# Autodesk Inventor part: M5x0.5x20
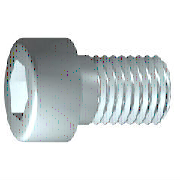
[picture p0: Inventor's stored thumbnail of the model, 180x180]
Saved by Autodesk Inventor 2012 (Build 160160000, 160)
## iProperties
IsCustomPart: 0
Company: 한국ATC센터
Created: 2014-07
Part Number: M5x0.5x20
Material: Steel, Mild
Description: 6각머리 태핑 나사
Document SubType Name: Modeling
Standard: KS B 1003
Designer: KYOUNG IL JANG
Standards Organization: KS
Language: ko-KR
Size Designation: M 5 x 20
Categories: <MemberInstance><Categories><Category DisplayName="조임쇠" InternalName="e4da775c-781d-43d5-af7c-5136215cf5a6" Mnemonic="FSTN"><Category DisplayName="볼트" InternalN
Density: 7.86 g/cm^3
Mass: 4.9629 g
Surface Area: 5.88237 cm^2
Volume: 0.631412 cm^3
Author: KYOUNG IL JANG
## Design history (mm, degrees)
body "Solid1"
workplane "Work Plane1"
fillet "Fillet2" dims "d30" = 0.1 (= R)
revolve "본체" stored, may be unused: angle "d10" = 90 deg
sketch "스케치2"
  geometry: L1 (0, -5.95)-(0, 5.95) reference; L2 (-5.95, 0)-(5.95, 0) reference; L3 (2.309, 0)-(1.155, -2); L4 (1.155, -2)-(-1.155, -2); L5 (-1.155, -2)-(-2.309, 0); L6 (-2.309, 0)-(-1.155, 2); L7 (-1.155, 2)-(1.155, 2); L8 (1.155, 2)-(2.309, 0); 2 further points
  constraints: 12 end point, 1 coincident, 1 horizontal alignment, 1 point on line, 12 other
extrude "슬롯" join sketch "스케치2" stored distance "d11" = 10; taper "d12" = 0 deg
fillet "모깎기1" dims "d17" = 0.5 (= RR)
feature "스레드" dims "d13" = 18 (= GEL), "d14" = 0
chamfer "모따기1" distance "d15" = 0.49076 (= -0.5 x SPD + 0.5 x GD); stored, may be unused: second distance "d16" = 0.49076 (= GUL), angle "d27" = 45 deg
sketch "스케치1"
  geometry: L1 (-1.167, 0)-(20, 0); L2 (20, 0)-(20, 2.5); L3 (20, 2.5)-(2, 2.5); L4 (2, 2.5)-(1.509, 2.5); L5 (1.509, 2.5)-(0, 2.5); L6 (0, 2.5)-(0, 4.25); L7 (0, 4.25)-(-5, 4.25); L8 (-5, 4.25)-(-5, 2.309); L9 (-5, 2.309)-(-2.5, 2.309); L10 (-2.5, 2.309)-(-1.167, 0); L11 (-10, 0)-(25, 0) reference; L12 (0, -0.85)-(0, 5.1) reference; L13 (2, 2.5)-(0, 2.5)
  constraints: 22 end point, 6 parallel, 2 collinear, 2 perpendicular, 1 horizontal, 1 point on line
  dimensions: "d1" = 18 distance from line of L3.end L2 (= GEL); "d2" = 0.49086 distance of L4.end L3.end (computed from GAL); "d3" = 5 distance between parallel lines of L8 L6 (= KOH); "d4" = 2.5 distance of L8.end L9.end (= INTI); "d5" = 60 deg angle of L10 L1; "d6" = 5 diameter of L3 L1 (= GD); "d7" = 5 diameter of L5 L1 (= BDM); "d8" = 4.6188 diameter of L9 L1 (= 1.1547 x SW); "d9" = 8.5 diameter of L7 L1 (= KOD); "d26" = 20 distance between parallel lines of L12 L2 (= NLG)
other parameters: "GD" = 5 (= NND) [user parameter; used in 2 equation terms], "NLG" = 20 [user parameter; used in 1 equation term], "GEL" = 18 [user parameter; used in 2 equation terms], "KOD" = 8.5 [user parameter; used in 1 equation term], "KOH" = 5 [user parameter; used in 1 equation term], "INTI" = 2.5 [user parameter; used in 1 equation term], "GAL" = 0.49076 (= 0.61345 x PTC) [user parameter; used in 1 equation term], "GUL" = 0.49076 (= 0.61345 x PTC) [user parameter; used in 1 equation term], "BDM" = 5 (= NND) [user parameter; used in 1 equation term], "SW" = 4 [user parameter; used in 2 equation terms], "RR" = 0.5 [user parameter; used in 1 equation term], "SPD" = 4.01848 (= NND - 1.2269 x PTC) [user parameter; used in 1 equation term], "d19" = 0, "d28" = 0, "d29" = 0, "R" = 0.1 [user parameter; used in 1 equation term], "PHH" = 0.2 [user parameter], "GD1" = 4.01848 (= THREADDIA - 1.2269 x PTC) [user parameter], "THREADDIA" = 5 [user parameter; used in 1 equation term], "FAWI" = 45 deg [user parameter], "TPU" = 12.5 (computed from PTC) [user parameter], "PTC" = 0.8 [user parameter; used in 5 equation terms], "NND" = 5 [user parameter; used in 3 equation terms], "TOA" = 30 deg [user parameter], "E0" = 4.62 (= 1.155 x SW) [user parameter]
